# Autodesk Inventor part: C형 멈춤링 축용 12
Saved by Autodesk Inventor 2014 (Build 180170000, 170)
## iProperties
Created: 2026-08
Part Number: C형 멈춤링 축용 12
Material: 강철, 연강
Document SubType Name: Modeling
Designer: dg
Density: 7.86 g/cm^3
Appearance: 강철
Mass: 0.56717 g
Surface Area: 2.44204 cm^2
Volume: 0.072159 cm^3
Author: jhkim
Description: 리테이닝 링(C형)
Creation Date: 2026-07-31
Sending System: Autodesk Inventor 2027
Preprocessor: ST-DEVELOPER v20.1
Author: dg
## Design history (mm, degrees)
node "C형 멈춤링 축용 121"
body "Solid1"
node "기준1"
